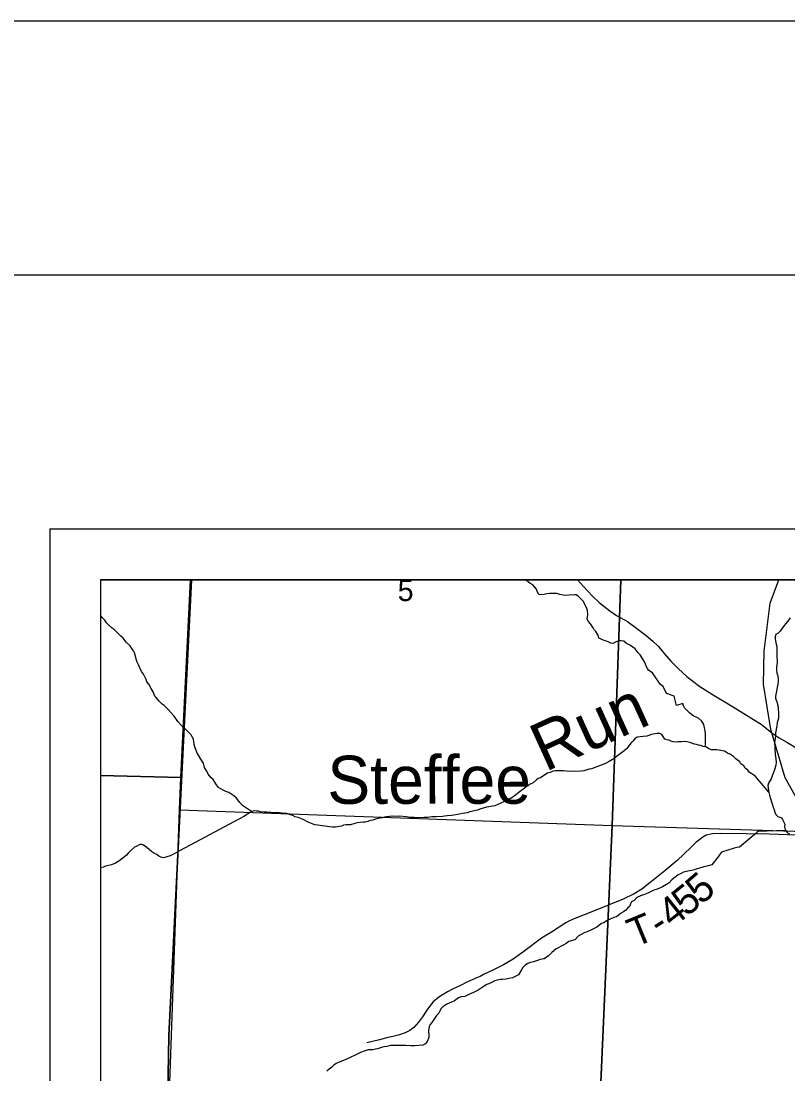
# Model space of a CAD drawing. Extents: x 0 to 34, y 0 to 22.
# Drawn here: x 1.944 to 3.454, y 19.927 to 22 of the extents above; entities that cross this region are included whole.
import ezdxf

# ---------------------------------------------------------------- set-up
doc = ezdxf.new("R2010")
doc.units = 0
for name, color, linetype in [('GM_X_Corporation', 7, 'Continuous'), ('GM_X_County_Road', 7, 'Continuous'), ('GM_X_Minor_River', 7, 'Continuous'), ('GM_X_Minor_River_Text', 7, 'Continuous'), ('GM_X_Rail_Line', 7, 'Continuous'), ('GM_X_Section_Text', 7, 'Continuous'), ('GM_X_Township_Road', 7, 'Continuous'), ('GM_X_Township_Road_Text', 7, 'Continuous'), ('SH_Border', 7, 'Continuous'), ('SH_Cut_Line', 7, 'Continuous'), ('SH_Data', 7, 'Continuous')]:
    doc.layers.add(name, color=color, linetype=linetype)

msp = doc.modelspace()

# ---------------------------------------------------------------- linework, layer by layer
at = {"layer": 'GM_X_Corporation'}
for points in [[(8.9, 20.9), (2.1, 20.9), (2.1, 16.4477), (2.1182, 16.4474), (2.1176, 16.4327), (2.1175, 16.4298), (2.1166, 16.4244), (2.1155, 16.4201), (2.2605, 16.4147), (2.3623, 16.41), (2.7707, 16.392), (3.0057, 16.3809), (3.6165, 16.3686), (3.7537, 16.3728), (3.9899, 16.3631), (4.4958, 16.358), (4.9914, 16.3477), (5.6931, 16.3352)], [(2.1894, 18.4715), (2.1995, 18.7384), (2.2038, 18.8576), (2.2042, 18.8835), (2.2075, 18.9201), (2.2151, 19.2353), (2.2155, 19.2474), (2.2163, 19.2747), (2.2173, 19.3051), (2.2174, 19.3106), (2.2185, 19.3474), (2.2301, 19.7293), (2.2346, 20.0021), (2.2795, 20.9), (2.1, 20.9), (2.1, 16.4477)], [(7.1302, 20.9), (2.2795, 20.9), (2.2346, 20.0021), (2.2301, 19.7293), (2.2185, 19.3474), (2.2174, 19.3106), (2.2173, 19.3051), (2.2163, 19.2747), (2.2155, 19.2474), (2.2151, 19.2353), (2.2075, 18.9201), (2.2042, 18.8835), (2.2038, 18.8576), (2.1995, 18.7384), (2.1894, 18.4715)]]:
    msp.add_lwpolyline(points, dxfattribs=at)
for points in [[(2.2774, 20.9), (2.1, 20.9), (2.1, 20.5146), (2.2584, 20.5106)], [(3.125, 20.9), (2.2774, 20.9), (2.2584, 20.5106), (2.2557, 20.4469), (3.1077, 20.4159)], [(4.1178, 20.9), (3.125, 20.9), (3.1077, 20.4159), (4.0987, 20.3855)], [(2.1, 20.5146), (2.1, 19.4892), (2.2214, 19.4847), (2.2557, 20.4469), (2.2584, 20.5106)], [(3.1077, 20.4159), (3.063, 19.4039), (2.2194, 19.4275), (2.2214, 19.4847), (2.2557, 20.4469)], [(3.1077, 20.4159), (4.0987, 20.3855), (4.0627, 19.3751), (3.063, 19.4039)]]:
    msp.add_lwpolyline(points, close=True, dxfattribs=at)
at = {"layer": 'GM_X_County_Road'}
msp.add_lwpolyline([(3.0394, 20.9), (3.0512, 20.8866), (3.0685, 20.8685), (3.0823, 20.8551), (3.1032, 20.8389), (3.1162, 20.8295), (3.1377, 20.8176), (3.1532, 20.8067), (3.1745, 20.7903), (3.188, 20.7788), (3.1988, 20.7682), (3.2099, 20.755), (3.2231, 20.7399), (3.2384, 20.7245), (3.2549, 20.7097), (3.2665, 20.7005), (3.2806, 20.69), (3.3089, 20.6722), (3.3364, 20.6556), (3.367, 20.6366), (3.3864, 20.625), (3.401, 20.6157), (3.4223, 20.5984), (3.4352, 20.5894), (3.4517, 20.5803), (3.4734, 20.5669)], dxfattribs=at)
at = {"layer": 'GM_X_Minor_River'}
for points in [[(3.2913, 20.5706), (3.2917, 20.5943), (3.2909, 20.6034), (3.2898, 20.6083), (3.2886, 20.6148), (3.2844, 20.6212), (3.2787, 20.6269), (3.2731, 20.6292), (3.2689, 20.6314), (3.2643, 20.6345), (3.2601, 20.6379), (3.2552, 20.6424), (3.2499, 20.6477), (3.248, 20.6515), (3.2472, 20.6564), (3.2343, 20.6526), (3.2297, 20.6708), (3.2146, 20.6761), (3.2081, 20.6894), (3.2031, 20.6939), (3.1952, 20.7045), (3.1914, 20.711), (3.1875, 20.7167), (3.1838, 20.7186), (3.1796, 20.7216), (3.1773, 20.7254), (3.1746, 20.7299), (3.1735, 20.7337), (3.1712, 20.7386), (3.1674, 20.7447), (3.1628, 20.7523), (3.159, 20.7557), (3.1529, 20.7637), (3.1484, 20.7671), (3.1442, 20.7705), (3.1358, 20.7746), (3.1305, 20.7792), (3.1252, 20.7799), (3.1203, 20.7795), (3.1146, 20.7769), (3.1093, 20.7742), (3.1052, 20.775), (3.101, 20.7768), (3.0964, 20.7787), (3.0919, 20.7802), (3.0862, 20.7829), (3.0816, 20.7848), (3.0801, 20.7905), (3.0759, 20.7977), (3.0721, 20.8015), (3.0706, 20.8052), (3.0653, 20.8128), (3.0607, 20.8181), (3.0588, 20.8227), (3.0592, 20.8265), (3.0599, 20.8318), (3.0591, 20.8394), (3.0576, 20.8432), (3.0549, 20.8504), (3.0504, 20.8576), (3.0454, 20.8633), (3.0412, 20.8667), (3.0367, 20.8701), (3.0329, 20.8701), (3.023, 20.8693), (3.0166, 20.8689), (3.0113, 20.8696), (3.0045, 20.8712), (2.9988, 20.8727), (2.9889, 20.873), (2.9844, 20.873), (2.9791, 20.8722), (2.9738, 20.8711), (2.967, 20.8703), (2.9632, 20.8711), (2.9605, 20.8752), (2.9586, 20.8817), (2.9514, 20.89), (2.9453, 20.8934), (2.94, 20.8976), (2.9348, 20.9)], [(2.3977, 20.4434), (2.38, 20.4555), (2.3747, 20.4616), (2.3679, 20.4699), (2.3629, 20.4745), (2.3565, 20.4786), (2.3527, 20.4809), (2.347, 20.4828), (2.3428, 20.4847), (2.3368, 20.4881), (2.3322, 20.4907), (2.3284, 20.4964), (2.3219, 20.5063), (2.3174, 20.5104), (2.3124, 20.5173), (2.3097, 20.5233), (2.3052, 20.5305), (2.3029, 20.5389), (2.2976, 20.5468), (2.293, 20.5548), (2.2903, 20.5586), (2.2861, 20.5707), (2.2846, 20.5756), (2.283, 20.5863), (2.2808, 20.5908), (2.2785, 20.5946), (2.2701, 20.6029), (2.2602, 20.612), (2.2526, 20.6207), (2.2454, 20.631), (2.2329, 20.645), (2.2256, 20.6526), (2.2218, 20.6552), (2.2158, 20.6609), (2.2097, 20.6681), (2.2066, 20.6723), (2.204, 20.6795), (2.2001, 20.6859), (2.1956, 20.6942), (2.1914, 20.6992), (2.1902, 20.7033), (2.1849, 20.7143), (2.1811, 20.7193), (2.175, 20.7325), (2.172, 20.7378), (2.1712, 20.7416), (2.1681, 20.7515), (2.167, 20.7557), (2.1654, 20.7602), (2.1616, 20.7648), (2.1586, 20.7697), (2.1506, 20.7769), (2.1445, 20.7852), (2.1404, 20.7886), (2.1312, 20.7981), (2.1271, 20.8019), (2.1229, 20.8049), (2.1168, 20.8106), (2.1122, 20.8151), (2.1084, 20.8204), (2.1039, 20.825), (2.1, 20.8297)], [(3.4582, 20.8249), (3.4536, 20.8181), (3.4495, 20.8139), (3.4468, 20.8101), (3.4434, 20.8052), (3.4385, 20.7987), (3.4344, 20.7949), (3.4302, 20.7922), (3.4287, 20.7877), (3.4287, 20.7839), (3.4295, 20.7797), (3.4306, 20.7729), (3.4322, 20.7683), (3.4322, 20.7626), (3.4318, 20.7577), (3.4322, 20.7513), (3.4322, 20.7475), (3.4326, 20.7406), (3.4326, 20.7368), (3.4319, 20.7327), (3.4311, 20.7281), (3.4315, 20.7224), (3.4323, 20.716), (3.4339, 20.7107), (3.4346, 20.7038), (3.435, 20.6993), (3.4343, 20.6943), (3.4328, 20.6879), (3.4317, 20.6807), (3.4302, 20.6742), (3.4294, 20.6704), (3.4294, 20.6666), (3.4306, 20.6625), (3.4325, 20.6583), (3.4336, 20.6537), (3.4344, 20.6492), (3.4348, 20.6443), (3.4352, 20.6389), (3.4356, 20.6321), (3.4352, 20.6276), (3.4341, 20.6226), (3.433, 20.6188), (3.4319, 20.612), (3.4293, 20.5987), (3.4293, 20.5945), (3.4285, 20.587), (3.4274, 20.5786), (3.4278, 20.571), (3.4282, 20.5672), (3.429, 20.5558), (3.4298, 20.5475), (3.4306, 20.5403), (3.4298, 20.5346), (3.4279, 20.5274), (3.4249, 20.5183), (3.4227, 20.5137), (3.4208, 20.5076), (3.4159, 20.4993), (3.4144, 20.4951), (3.4148, 20.4905), (3.4159, 20.4845), (3.4163, 20.4807), (3.4175, 20.4758), (3.4213, 20.4629), (3.4236, 20.4568), (3.4251, 20.4522), (3.427, 20.4469), (3.4282, 20.4424), (3.4301, 20.4378), (3.4339, 20.434), (3.4377, 20.4325), (3.4415, 20.4314), (3.443, 20.4276), (3.4461, 20.4227), (3.448, 20.4185), (3.4472, 20.4143), (3.448, 20.4102), (3.4499, 20.4064), (3.4526, 20.4022), (3.4567, 20.3996)], [(3.4162, 20.4815), (3.3905, 20.5121), (3.3867, 20.5152), (3.3825, 20.5178), (3.3776, 20.5212), (3.3749, 20.525), (3.3696, 20.5288), (3.3669, 20.5333), (3.3612, 20.5375), (3.3589, 20.5417), (3.3513, 20.5473), (3.3464, 20.5519), (3.3392, 20.5564), (3.3346, 20.5587), (3.3289, 20.5625), (3.3248, 20.5632), (3.3187, 20.5644), (3.3142, 20.5647), (3.3081, 20.5647), (3.3035, 20.5651), (3.2982, 20.567), (3.2933, 20.57), (3.2869, 20.5719), (3.2827, 20.5738), (3.2781, 20.5745), (3.274, 20.5753), (3.2698, 20.5764), (3.2607, 20.5794), (3.255, 20.5809), (3.2505, 20.5813), (3.2444, 20.5809), (3.2372, 20.5805), (3.2334, 20.5801), (3.2281, 20.5805), (3.2239, 20.5824), (3.2198, 20.5839), (3.216, 20.5847), (3.2114, 20.5858), (3.2084, 20.5911), (3.2053, 20.5949), (3.2015, 20.5975), (3.1962, 20.5972), (3.1849, 20.5949), (3.1803, 20.5933), (3.1762, 20.5918), (3.169, 20.591), (3.1629, 20.5903), (3.1568, 20.5899), (3.1523, 20.5868), (3.1485, 20.5823), (3.1444, 20.5781), (3.1395, 20.5712), (3.1357, 20.5671), (3.1312, 20.5629), (3.1259, 20.5591), (3.1183, 20.5534), (3.1126, 20.5484), (3.1081, 20.5461), (3.102, 20.5423), (3.0945, 20.5381), (3.0861, 20.5347), (3.0774, 20.5313), (3.0672, 20.5279), (3.0623, 20.5267), (3.0521, 20.5236), (3.046, 20.5229), (3.035, 20.5225), (3.0305, 20.5228), (3.024, 20.5225), (3.0176, 20.5232), (3.0119, 20.5236), (3.0077, 20.5239), (3.0024, 20.5239), (2.996, 20.5235), (2.9918, 20.5232), (2.9854, 20.5201), (2.9801, 20.519), (2.9714, 20.5132), (2.9669, 20.5102), (2.9623, 20.5083), (2.9582, 20.5053), (2.9521, 20.4999), (2.946, 20.4973), (2.9381, 20.4919), (2.9317, 20.487), (2.9249, 20.4817), (2.9177, 20.476), (2.9079, 20.4695), (2.901, 20.4672), (2.8965, 20.4638), (2.8886, 20.46), (2.8768, 20.455), (2.8719, 20.4539), (2.8647, 20.4527), (2.8605, 20.4523), (2.8537, 20.45), (2.8473, 20.4481), (2.8427, 20.4462), (2.8276, 20.4432), (2.8223, 20.4412), (2.8128, 20.4397)], [(2.8128, 20.4397), (2.8072, 20.4382), (2.803, 20.4374), (2.7958, 20.4366), (2.7912, 20.4355), (2.7825, 20.4351), (2.7776, 20.4343), (2.7738, 20.4339), (2.7602, 20.4328), (2.7526, 20.4328), (2.745, 20.432), (2.7374, 20.432), (2.7272, 20.4312), (2.7181, 20.4316), (2.7105, 20.4319), (2.7018, 20.433), (2.6897, 20.4342), (2.6848, 20.4338), (2.6772, 20.4345), (2.6692, 20.4337), (2.6636, 20.4333), (2.6594, 20.4322), (2.6545, 20.431), (2.6503, 20.4307), (2.642, 20.4287), (2.6367, 20.4268), (2.631, 20.4257), (2.6264, 20.4238), (2.6215, 20.4226), (2.6177, 20.4226), (2.6113, 20.4219), (2.606, 20.4215), (2.6011, 20.4199), (2.5924, 20.4176), (2.5836, 20.4176), (2.5787, 20.4169), (2.5746, 20.415), (2.5632, 20.4127), (2.5571, 20.413), (2.5465, 20.4141), (2.5325, 20.416), (2.5279, 20.4164), (2.5219, 20.4175), (2.5154, 20.4198), (2.509, 20.4228), (2.4995, 20.4277), (2.4896, 20.4315), (2.4832, 20.4334), (2.479, 20.436), (2.4722, 20.4379), (2.4669, 20.4394), (2.4581, 20.4405), (2.4521, 20.4409), (2.4403, 20.4412), (2.4354, 20.4416), (2.4316, 20.4416), (2.4267, 20.4424), (2.4221, 20.4423), (2.4153, 20.4431), (2.4111, 20.4442), (2.407, 20.4442), (2.4024, 20.4446), (2.3983, 20.4438), (2.3899, 20.4385), (2.3824, 20.4335), (2.2568, 20.3665), (2.2522, 20.3642), (2.2424, 20.3589), (2.2375, 20.3566), (2.231, 20.3543), (2.225, 20.3524), (2.2208, 20.3528), (2.2147, 20.3554), (2.2109, 20.3588), (2.2052, 20.3615), (2.2014, 20.3641), (2.1969, 20.3683), (2.1916, 20.3724), (2.1847, 20.377), (2.1802, 20.3793), (2.176, 20.3777), (2.1719, 20.3754), (2.1673, 20.3732), (2.1594, 20.3663), (2.1552, 20.3625), (2.1507, 20.3572), (2.145, 20.3526), (2.139, 20.3481), (2.1348, 20.345), (2.1295, 20.3416), (2.1216, 20.3389), (2.1102, 20.3359), (2.106, 20.3339), (2.1, 20.3324)], [(3.4499, 20.4063), (3.3942, 20.4044), (3.3904, 20.4006), (3.3583, 20.3736), (3.3534, 20.3724), (3.3481, 20.3717), (3.3231, 20.3633), (3.3189, 20.3583), (3.3167, 20.3541), (3.3038, 20.3389), (3.2944, 20.3359), (3.2883, 20.3347), (3.2841, 20.3332), (3.2743, 20.3305), (3.2698, 20.329), (3.2645, 20.3275), (3.2569, 20.326), (3.2485, 20.324), (3.2436, 20.3214), (3.238, 20.3191), (3.2338, 20.3157), (3.2293, 20.3126), (3.2255, 20.3088), (3.2202, 20.3031), (3.2149, 20.2997), (3.2066, 20.2951), (3.1982, 20.2913), (3.1941, 20.2902), (3.1895, 20.2886), (3.1782, 20.2829), (3.1714, 20.2799), (3.1634, 20.2776), (3.1562, 20.2745), (3.1513, 20.2685), (3.1456, 20.2658), (3.1438, 20.2616), (3.1423, 20.2574), (3.1381, 20.2533), (3.1347, 20.2495), (3.1302, 20.246), (3.1256, 20.2434), (3.1166, 20.2365), (3.1113, 20.235), (3.098, 20.2293), (3.0916, 20.2243), (3.087, 20.2232), (3.0776, 20.2156), (3.07, 20.2118), (3.0587, 20.2064), (3.0537, 20.2053), (3.0409, 20.1981), (3.0341, 20.1908), (3.0227, 20.1874), (3.0174, 20.1836), (3.0125, 20.1813), (2.9978, 20.1729), (2.9928, 20.1691), (2.9887, 20.1657), (2.9826, 20.1592), (2.9739, 20.1535), (2.966, 20.152), (2.9607, 20.1501), (2.9531, 20.1478), (2.9471, 20.1463), (2.9414, 20.1444), (2.9365, 20.1413), (2.9319, 20.1364), (2.9289, 20.1318), (2.9233, 20.1223), (2.9115, 20.1162), (2.9043, 20.1151), (2.899, 20.1135), (2.8918, 20.1131), (2.8877, 20.1128), (2.8816, 20.1116), (2.8767, 20.1101), (2.865, 20.1044), (2.8608, 20.1028), (2.8555, 20.0994), (2.8442, 20.0918), (2.8347, 20.0869), (2.8256, 20.083), (2.8214, 20.0815), (2.8173, 20.0796), (2.8101, 20.0788), (2.8052, 20.0769), (2.7972, 20.0708), (2.7915, 20.0682), (2.7821, 20.064), (2.7745, 20.059), (2.7704, 20.0549), (2.7681, 20.0507), (2.7662, 20.0465), (2.7617, 20.0416), (2.7568, 20.034), (2.7526, 20.0279), (2.7492, 20.0241), (2.7474, 20.0203), (2.7459, 20.0115), (2.747, 20.0047), (2.7467, 19.9983)], [(2.7467, 19.9983), (2.7436, 19.9907), (2.7399, 19.9861), (2.735, 19.9838), (2.7194, 19.9823), (2.7111, 19.9819), (2.7012, 19.9826), (2.6963, 19.9826), (2.6868, 19.983), (2.6827, 19.983), (2.677, 19.9826), (2.6717, 19.9826), (2.6641, 19.9807), (2.658, 19.9799), (2.6535, 19.9787), (2.6459, 19.9764), (2.6418, 19.9757), (2.6365, 19.9745), (2.6323, 19.9745), (2.627, 19.9741), (2.6194, 19.9718), (2.6122, 19.9692), (2.6016, 19.9638), (2.5929, 19.96), (2.588, 19.9574), (2.5751, 19.952), (2.5698, 19.9501), (2.5642, 19.9474), (2.5596, 19.944), (2.5555, 19.9402), (2.5506, 19.936), (2.546, 19.9322)]]:
    msp.add_lwpolyline(points, dxfattribs=at)
at = {"layer": 'GM_X_Rail_Line'}
msp.add_lwpolyline([(4.8515, 18.4096), (4.468, 18.9077), (4.382, 19.0334), (4.1748, 19.3749), (3.8527, 19.8843), (3.6877, 20.1234), (3.6615, 20.1661), (3.5505, 20.339), (3.4927, 20.4317), (3.4483, 20.5097), (3.4202, 20.6049), (3.4057, 20.6941), (3.4068, 20.7593), (3.4191, 20.8537), (3.4357, 20.9)], dxfattribs=at)
at = {"layer": 'GM_X_Township_Road'}
msp.add_lwpolyline([(3.4727, 20.3969), (3.4533, 20.3975), (3.4179, 20.3991), (3.3716, 20.3995), (3.3213, 20.4005), (3.3056, 20.3998), (3.2926, 20.3967), (3.2864, 20.3931), (3.2805, 20.3887), (3.2733, 20.3831), (3.263, 20.3728), (3.2356, 20.3469), (3.2112, 20.3266), (3.185, 20.3055), (3.1665, 20.2909), (3.1513, 20.2814), (3.1293, 20.2711), (3.0712, 20.2475), (3.034, 20.2326), (3.0237, 20.228), (3.0165, 20.2241), (3.0035, 20.2159), (2.988, 20.2062), (2.9685, 20.1941), (2.9336, 20.1682), (2.9128, 20.1528), (2.8938, 20.1417), (2.8725, 20.1312), (2.8545, 20.1224), (2.8477, 20.119), (2.8405, 20.1163), (2.8352, 20.1132), (2.8288, 20.1109), (2.8216, 20.1075), (2.8091, 20.1009), (2.7947, 20.0942), (2.7834, 20.0883), (2.7662, 20.0783), (2.7552, 20.0691), (2.7441, 20.0544), (2.7344, 20.0393), (2.7262, 20.0288), (2.7174, 20.0185), (2.7095, 20.0121), (2.7002, 20.0077), (2.6887, 20.0036), (2.6756, 20.0008), (2.6658, 19.9985), (2.6497, 19.9941), (2.6247, 19.9884)], dxfattribs=at)
at = {"layer": 'SH_Border'}
msp.add_lwpolyline([(1.5, 21.5), (33.5, 21.5), (33.5, 0.5), (1.5, 0.5)], close=True, dxfattribs=at)
at = {"layer": 'SH_Cut_Line'}
msp.add_lwpolyline([(0, 0), (34, 0), (34, 22), (0, 22)], close=True, dxfattribs=at)
at = {"layer": 'SH_Data'}
for p, q in [((2, 21), (9, 21)), ((2, 21), (2, 14)), ((2.1, 20.9), (2.1, 14.1)), ((2.1, 20.9), (8.9, 20.9))]:
    msp.add_line(p, q, dxfattribs=at)

# ---------------------------------------------------------------- texts
at = {"layer": 'GM_X_Minor_River_Text'}
for s, height, rotation, p in [('Run', 0.09469, 24.4644, (2.9757, 20.5208)), ('Steffee', 0.0947, 0.0369, (2.5468, 20.4587))]:
    msp.add_text(s, height=height, rotation=rotation, dxfattribs=at).set_placement(p)
at = {"layer": 'GM_X_Section_Text'}
msp.add_text('5', height=0.0419, rotation=0, dxfattribs=at).set_placement((2.6854, 20.8579))
at = {"layer": 'GM_X_Township_Road_Text'}
for s, rotation, p in [('5', 40.8667, (3.2831, 20.2584)), ('5', 38.9642, (3.2543, 20.2351)), ('4', 38.553, (3.2265, 20.213)), ('T', 22.337, (3.1524, 20.1755)), ('-', 32.1823, (3.2012, 20.1965))]:
    msp.add_text(s, height=0.0568, rotation=rotation, dxfattribs=at).set_placement(p)

doc.saveas('drawing.dxf')
